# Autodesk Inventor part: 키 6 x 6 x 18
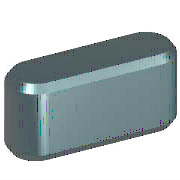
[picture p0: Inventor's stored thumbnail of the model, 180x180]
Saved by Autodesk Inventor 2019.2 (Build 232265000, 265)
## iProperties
IsCustomPart: 1
Created: 2012-02
Part Number: 키 6 x 6 x 18
Material: 강철, 연강
Description: 키 및 해당 키홈
Document SubType Name: Modeling
Standard: KS B 1311
Designer: mduedu
Standards Organization: KS
Language: ko-KR
Size Designation: 6 x 6 x 18
Categories: <MemberInstance><Categories><Category DisplayName="샤프트 부품" InternalName="7f7aeb1f-a693-4053-b835-cee3144e0d98" Mnemonic="SHFT"><Category DisplayName="키" Interna
Density: 1 g/cm^3
Appearance: 노란색
Author: mduedu
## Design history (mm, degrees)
workplane "Work Plane1"
workplane "Work Plane2"
sketch "스케치1"
  geometry: L1 (3, 3)-(15, 3); L2 (15, -3)-(3, -3); L3 (0, 9.4)-(0, -7.4) reference; L4 (-5, 0)-(30, 0) reference; L5 (18, 0)-(18, 7); A1 r 3 centre (3, 0) between (3, 3) and (3, -3); A2 r 3 centre (15, 0) between (15, -3) and (15, 3)
  constraints: 6 end point, 5 point on circle, 4 tangent, 3 point on line, 2 centre point, 1 horizontal, 1 parallel, 1 perpendicular
  dimensions: "d0" = 3 radius of A1 (= 0.5 x PB); "d13" = 3 radius of A2 (= 0.5 x PB); "d14" = 18 distance between parallel lines of L5 L3 (= NLG)
extrude "본체1" new body sketch "스케치1" taper "d3" = 0 deg; stored distance "d4" = 10
workplane "Work Plane3"
body "Solid1"
chamfer "모따기1" distance "d8" = 0.4 (= PHH); stored, may be unused: second distance "d9" = 0.4 (= PHH), angle "d15" = 45 deg
other parameters: "d1" = -3.5 (= -PNT), "d2" = 2.5 (= PH - PNT), "NLG" = 18 [user parameter; used in 3 equation terms], "PB" = 6 [user parameter; used in 2 equation terms], "PNT" = 3.5 [user parameter; used in 2 equation terms], "PH" = 6 [user parameter; used in 1 equation term], "PHH" = 0.4 [user parameter; used in 2 equation terms], "d10" = 0, "d16" = 0, "d17" = 0, "d18" = 0, "WDMIN" = 17 [user parameter], "PLB2" = 18 (= NLG) [user parameter], "WDMAX" = 22 [user parameter], "PLB1" = 18 (= NLG) [user parameter], "RR" = 0.16 [user parameter], "PUEB" = 2.8 [user parameter]
